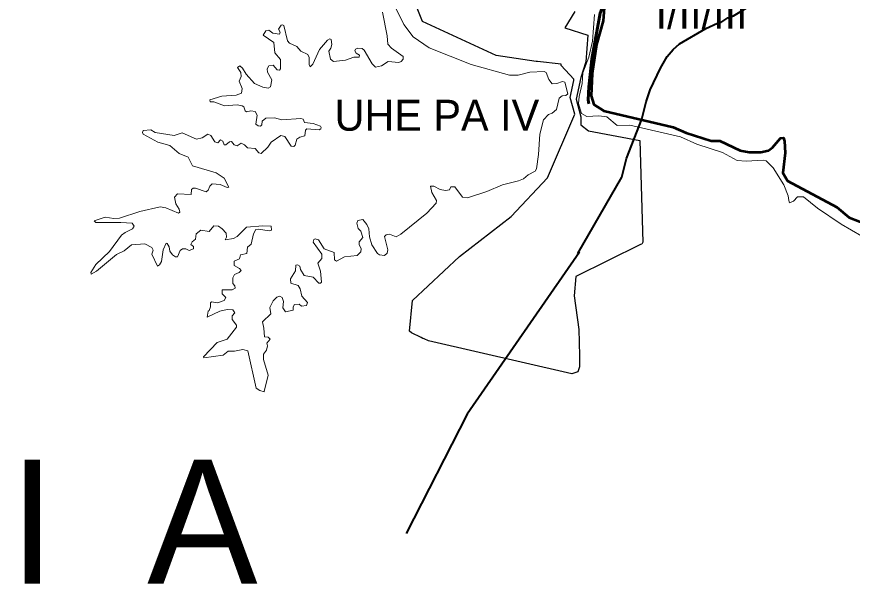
# Model space of a CAD drawing. Extents: x -1643653 to 4543381, y 1624270 to 13878484.
# Drawn here: x 578068 to 591570, y 8951061 to 8960281 of the extents above; entities that cross this region are included whole.
import ezdxf
from ezdxf.enums import TextEntityAlignment as Align

# ---------------------------------------------------------------- set-up
doc = ezdxf.new("R2010")
doc.units = 0
doc.header["$LTSCALE"] = 200
doc.linetypes.add('LONG_DASH_SHORT_DASH', pattern=[9.9, 6, -1.2, 1.5, -1.2])
for name, color, linetype, lineweight in [('12', 7, 'Continuous', 25), ('21', 7, 'Continuous', 25), ('25', 7, 'Continuous', 13), ('28', 7, 'Continuous', 53), ('60', 7, 'Continuous', 13), ('7', 7, 'LONG_DASH_SHORT_DASH', 60)]:
    doc.layers.add(name, color=color, linetype=linetype, lineweight=lineweight)
doc.layers.add('42', color=7, linetype='Continuous')

msp = doc.modelspace()

# ---------------------------------------------------------------- linework, layer by layer
at = {"layer": '12', "lineweight": 40}
for points in [[(587134, 8956453.8), (587843.6, 8957685.7), (587923.7, 8957988.5), (588169.9, 8958625.1), (588237, 8958904.7), (588304.1, 8959099.5), (588468, 8959448.9), (588578.9, 8959635.8), (588673.7, 8959750.1), (588777.5, 8959843.1), (589203.6, 8960089.7), (589393.4, 8960175.8), (589428.5, 8960178.5), (589560.1, 8960264.6), (589648.9, 8960297.2), (590059.4, 8960543.5), (591188.1, 8961101.4), (591408.7, 8961235.4), (591525.3, 8961280.9), (591868.7, 8961488.1), (592154.1, 8961587.2), (592311.1, 8961655)], [(587162.9, 8956477.1), (585344.2, 8953858.6), (584358.8, 8951929.6)]]:
    msp.add_lwpolyline(points, dxfattribs=at)
at = {"layer": '21'}
for points in [[(586058.4, 8957052.4), (586644.6, 8957678.4), (587088.5, 8958707.8), (587013.2, 8958975.6), (587068.3, 8959252.8), (587068.3, 8959273), (586866.5, 8959495), (586866.5, 8959515.2), (586483.1, 8959555.5), (586463, 8959555.5), (585817.3, 8959656.5), (584626.8, 8960201.4), (584162.8, 8961372.1)], [(587088.5, 8960362.9), (586927, 8960100.5)], [(586927, 8960100.5), (587293.7, 8959984.2), (587261.8, 8959553.8), (587182.2, 8959298.7), (587110, 8958948.6), (587182.2, 8958662.7), (587182.2, 8958533.5), (587309.6, 8958437.9), (588138.3, 8958278.5)], [(588138.3, 8958278.5), (588184.9, 8956636.2), (588170.1, 8956606.6), (588147.9, 8956599.2), (587104, 8956080.8), (587074.4, 8955769.7), (587148.4, 8955229.1)], [(587148.4, 8955229.1), (587155.8, 8955021.8), (587155.8, 8954992.1), (587163.2, 8954829.2), (587163.2, 8954644.1), (587163.2, 8954621.8), (587133.6, 8954540.4), (587037.4, 8954510.8), (584720.1, 8955044), (584653.5, 8955073.6), (584631.3, 8955081), (584601.7, 8955095.8), (584446.2, 8955169.9), (584416.6, 8955199.5), (584461, 8955695.7), (585223.6, 8956406.6), (586058.4, 8957052.4)]]:
    msp.add_lwpolyline(points, dxfattribs=at)
at = {"layer": '25'}
for points in [[(584187.7, 8960432.6), (584325.6, 8960152.6), (584476.5, 8959954.9), (584733.5, 8959776.4), (585408.8, 8959506.7), (586028.5, 8959334.8), (586169.5, 8959338.8), (586356.5, 8959383.4), (586592.2, 8959394), (586621.9, 8959377), (586666.5, 8959264.6), (586719.8, 8959198.7), (586794.3, 8959202.9), (586887.5, 8959234.6), (586924.3, 8959221.3), (586974.5, 8959033.2), (586938.3, 8959007.4), (586883.3, 8959001), (586832.3, 8958962.8), (586791.8, 8958780.2), (586717.8, 8958720.8), (586660.1, 8958701.3), (586577.3, 8958614.2), (586518, 8958381), (586500.9, 8958053.6), (586466.9, 8957824.2), (586445.4, 8957783.8), (586330.8, 8957724.2), (586254.3, 8957662.7), (586173.8, 8957626.7)], [(584187.7, 8960432.6), (584325.6, 8960152.6), (584476.5, 8959954.9), (584733.5, 8959776.4), (585408.8, 8959506.7), (586028.5, 8959334.8), (586169.5, 8959338.8), (586356.5, 8959383.4), (586592.2, 8959394), (586621.9, 8959377), (586666.5, 8959264.6), (586719.8, 8959198.7), (586794.3, 8959202.9), (586887.5, 8959234.6), (586924.3, 8959221.3), (586974.5, 8959033.2), (586938.3, 8959007.4), (586883.3, 8959001), (586832.3, 8958962.8), (586791.8, 8958780.2), (586717.8, 8958720.8), (586660.1, 8958701.3), (586577.3, 8958614.2), (586518, 8958381), (586500.9, 8958053.6), (586466.9, 8957824.2), (586445.4, 8957783.8), (586330.8, 8957724.2), (586254.3, 8957662.7), (586173.8, 8957626.7)], [(582299.4, 8960082.5), (582339.6, 8960143.8), (582362.8, 8960152.2), (582381.9, 8960139.6), (582443.6, 8959893.3), (582477.6, 8959853), (582596.3, 8959797.7), (582656.1, 8959725.5), (582771.8, 8959670.2), (582795.6, 8959619.4), (582792, 8959510.9), (582809, 8959470.7), (582851.4, 8959515.1), (582957.8, 8959753.2), (583089.5, 8959901.9), (583125.3, 8959922.9), (583148.8, 8959914.2), (583159.4, 8959833.8), (583144.6, 8959774.5), (583108.6, 8959723.3), (583108.6, 8959723.3), (583138.3, 8959595.9), (583184.5, 8959559.9), (583382, 8959578.8), (583514.4, 8959627.7), (583603.4, 8959628), (583607.5, 8959661.8), (583550.2, 8959691.6), (583531.3, 8959731.8), (583541.6, 8959757), (583580.3, 8959774.3), (583651.7, 8959765.9), (583684, 8959740.2), (583809.5, 8959521.5), (583862.6, 8959466.3), (583962.4, 8959487.6), (584070.6, 8959557.6), (584244.7, 8959542.8), (584281, 8959557.7), (584312.8, 8959595.8), (584315, 8959638.2), (584126, 8959774.3), (584064.3, 8959836.4), (584055.9, 8959969.5), (583979.3, 8960356.6)], [(582299.4, 8960082.5), (582339.6, 8960143.8), (582362.8, 8960152.2), (582381.9, 8960139.6), (582443.6, 8959893.3), (582477.6, 8959853), (582596.3, 8959797.7), (582656.1, 8959725.5), (582771.8, 8959670.2), (582795.6, 8959619.4), (582792, 8959510.9), (582809, 8959470.7), (582851.4, 8959515.1), (582957.8, 8959753.2), (583089.5, 8959901.9), (583125.3, 8959922.9), (583148.8, 8959914.2), (583159.4, 8959833.8), (583144.6, 8959774.5), (583108.6, 8959723.3), (583108.6, 8959723.3), (583138.3, 8959595.9), (583184.5, 8959559.9), (583382, 8959578.8), (583514.4, 8959627.7), (583603.4, 8959628), (583607.5, 8959661.8), (583550.2, 8959691.6), (583531.3, 8959731.8), (583541.6, 8959757), (583580.3, 8959774.3), (583651.7, 8959765.9), (583684, 8959740.2), (583809.5, 8959521.5), (583862.6, 8959466.3), (583962.4, 8959487.6), (584070.6, 8959557.6), (584244.7, 8959542.8), (584281, 8959557.7), (584312.8, 8959595.8), (584315, 8959638.2), (584126, 8959774.3), (584064.3, 8959836.4), (584055.9, 8959969.5), (583979.3, 8960356.6)], [(587403.7, 8960314.5), (587373.8, 8959887.7), (587311.1, 8959628.3), (587213.9, 8959375.4), (587204.9, 8959204), (587155.6, 8958993.5), (587145.5, 8958878.4), (587193.6, 8958719.2), (587281.8, 8958666.6), (587474.7, 8958681.2), (587603.9, 8958663), (587767.8, 8958525.1), (587976.7, 8958527.1), (588793.4, 8958337.9), (589059.2, 8958220.1), (589471.1, 8958087), (589708, 8957957.9), (589856.5, 8957947.6), (590127.1, 8957964.8), (590176.9, 8957951.8), (590291.3, 8957841.5), (590464.7, 8957564.3), (590533, 8957388.3), (590544.4, 8957313.3), (590557.7, 8957273.4), (590617.6, 8957300), (590684.2, 8957372.3), (590781.5, 8957369.6), (591005.6, 8957189.1), (591390.8, 8956926.9), (591724.8, 8956737.2)], [(587368.2, 8959365.5), (587437, 8959830.7), (587541.6, 8960215), (587558.8, 8960425)], [(580099.6, 8958407.9), (580098.5, 8958410.3), (580113.2, 8958444.3), (580235.9, 8958453.9), (580303, 8958410.4), (580612.5, 8958359.6), (580740.2, 8958401.9), (580973.9, 8958304.4), (581064.7, 8958323.4), (581156.5, 8958384.9), (581203.2, 8958359.3), (581270.9, 8958257.8), (581319.8, 8958245), (581360.2, 8958291.4), (581400.5, 8958268.1), (581420.4, 8958210.8), (581447.3, 8958208.8), (581504.7, 8958259.6), (581539.6, 8958263.8), (581539.6, 8958263.8), (581578.9, 8958209), (581627.9, 8958191.9), (581696, 8958236.1), (581748.9, 8958212.8), (581799.4, 8958164.3), (581920, 8958154), (581978.5, 8958081.4), (582019.4, 8958072.8), (582127.2, 8958170.8), (582178.1, 8958253.3), (582332.9, 8958361.5), (582401, 8958344.6), (582505.1, 8958189.8), (582543.4, 8958185.4), (582568.8, 8958204.3), (582596.6, 8958300), (582641.2, 8958331.9), (582721.7, 8958357.6), (582732.5, 8958448.5), (582755.7, 8958467.7), (582953.2, 8958455.2), (582983.1, 8958470.1), (582989.4, 8958491.2), (582974.4, 8958510.4), (582859.9, 8958554.9), (582719.7, 8958570.1), (582696.2, 8958625.2), (582656.2, 8958635.6), (582353.6, 8958614.5), (582235.7, 8958646.3), (582095.5, 8958639.9), (582031.7, 8958591.2), (582027, 8958531.6), (582005.7, 8958514.7), (581967.3, 8958516.9), (581933.7, 8958544.9), (581955, 8958692.5), (581922.9, 8958748.3), (581848.8, 8958761), (581780.6, 8958746.3), (581757.5, 8958761.1), (581738.2, 8958822.6), (581712.6, 8958841.7), (581627.9, 8958854.5), (581424.2, 8958839.7), (581251.8, 8958907.5), (581194.6, 8958907.9), (581190.6, 8958937.3), (581381.2, 8958994.6), (581615.1, 8959015.9), (581699.9, 8959047.7), (581708.6, 8959122.1), (581659.8, 8959239), (581692.1, 8959315.5), (581691.6, 8959378.9), (581634.5, 8959460), (581670.4, 8959485.2), (581717.2, 8959451.2), (581774.6, 8959353.5), (581908.3, 8959202.9), (582046.5, 8959141.3), (582129.4, 8959128.6), (582167.3, 8959147.5), (582188.6, 8959260.2), (582118.7, 8959385.4), (582116.5, 8959440.5), (582142.1, 8959487.4), (582214.1, 8959495.9), (582278, 8959423.9), (582316.1, 8959415.5), (582331, 8959439.1), (582330.8, 8959589.7), (582237.6, 8959695.7), (582220.4, 8959865.6), (582050.7, 8959980.4), (582091.2, 8960052.6), (582141.7, 8960063.2), (582208.1, 8960016.5), (582315.9, 8960001.7), (582322.5, 8960029), (582299.4, 8960082.5)], [(580099.6, 8958407.9), (580098.5, 8958410.3), (580113.2, 8958444.3), (580235.9, 8958453.9), (580303, 8958410.4), (580612.5, 8958359.6), (580740.2, 8958401.9), (580973.9, 8958304.4), (581064.7, 8958323.4), (581156.5, 8958384.9), (581203.2, 8958359.3), (581270.9, 8958257.8), (581319.8, 8958245), (581360.2, 8958291.4), (581400.5, 8958268.1), (581420.4, 8958210.8), (581447.3, 8958208.8), (581504.7, 8958259.6), (581539.6, 8958263.8), (581539.6, 8958263.8), (581578.9, 8958209), (581627.9, 8958191.9), (581696, 8958236.1), (581748.9, 8958212.8), (581799.4, 8958164.3), (581920, 8958154), (581978.5, 8958081.4), (582019.4, 8958072.8), (582127.2, 8958170.8), (582178.1, 8958253.3), (582332.9, 8958361.5), (582401, 8958344.6), (582505.1, 8958189.8), (582543.4, 8958185.4), (582568.8, 8958204.3), (582596.6, 8958300), (582641.2, 8958331.9), (582721.7, 8958357.6), (582732.5, 8958448.5), (582755.7, 8958467.7), (582953.2, 8958455.2), (582983.1, 8958470.1), (582989.4, 8958491.2), (582974.4, 8958510.4), (582859.9, 8958554.9), (582719.7, 8958570.1), (582696.2, 8958625.2), (582656.2, 8958635.6), (582353.6, 8958614.5), (582235.7, 8958646.3), (582095.5, 8958639.9), (582031.7, 8958591.2), (582027, 8958531.6), (582005.7, 8958514.7), (581967.3, 8958516.9), (581933.7, 8958544.9), (581955, 8958692.5), (581922.9, 8958748.3), (581848.8, 8958761), (581780.6, 8958746.3), (581757.5, 8958761.1), (581738.2, 8958822.6), (581712.6, 8958841.7), (581627.9, 8958854.5), (581424.2, 8958839.7), (581251.8, 8958907.5), (581194.6, 8958907.9), (581190.6, 8958937.3), (581381.2, 8958994.6), (581615.1, 8959015.9), (581699.9, 8959047.7), (581708.6, 8959122.1), (581659.8, 8959239), (581692.1, 8959315.5), (581691.6, 8959378.9), (581634.5, 8959460), (581670.4, 8959485.2), (581717.2, 8959451.2), (581774.6, 8959353.5), (581908.3, 8959202.9), (582046.5, 8959141.3), (582129.4, 8959128.6), (582167.3, 8959147.5), (582188.6, 8959260.2), (582118.7, 8959385.4), (582116.5, 8959440.5), (582142.1, 8959487.4), (582214.1, 8959495.9), (582278, 8959423.9), (582316.1, 8959415.5), (582331, 8959439.1), (582330.8, 8959589.7), (582237.6, 8959695.7), (582220.4, 8959865.6), (582050.7, 8959980.4), (582091.2, 8960052.6), (582141.7, 8960063.2), (582208.1, 8960016.5), (582315.9, 8960001.7), (582322.5, 8960029), (582299.4, 8960082.5)], [(591853.4, 8956904.4), (591520.9, 8957037.4), (591321.1, 8957200.7), (590522.6, 8957630), (590445.4, 8957756.5), (590486.6, 8958082.5), (590475.5, 8958269.4), (590460, 8958322.7), (590411.3, 8958320.8), (590281.4, 8958169.9), (590213.4, 8958120.7), (590089.5, 8958093.2), (589901.7, 8958091.4), (589756.1, 8958120.1), (589428.5, 8958275.3), (589288.6, 8958277.6), (588883.2, 8958402.7), (588677.6, 8958496.7), (587555.9, 8958762.2), (587392.7, 8958862), (587351, 8959003.1), (587368.2, 8959365.5)], [(579330.4, 8956970.9), (579320.1, 8956982.2), (579494.9, 8957040.3), (579635.1, 8957021.3), (579729, 8957025.6), (580056.8, 8957131.9), (580383.3, 8957210.3), (580477.4, 8957190.9), (580682.8, 8957104.2), (580701.6, 8957122.8), (580693.2, 8957169.7), (580640, 8957259.4), (580619.2, 8957363.6), (580667.8, 8957416.2), (580886.3, 8957410), (580890.9, 8957486.6), (580919.1, 8957507.7), (580955.2, 8957509.6), (581130.8, 8957450.5), (581162.8, 8957476.1), (581188.5, 8957544.2), (581224.5, 8957577.8), (581357.9, 8957571.4), (581466.2, 8957520.6), (581496, 8957526.9), (581421.8, 8957673.3), (581289.9, 8957760.6), (580910.1, 8957870.9), (580835.5, 8958013.2), (580692.5, 8958073.2), (580540.2, 8958198), (580349.1, 8958255.5), (580111.4, 8958382.8), (580099.6, 8958407.9)], [(579330.4, 8956970.9), (579320.1, 8956982.2), (579494.9, 8957040.3), (579635.1, 8957021.3), (579729, 8957025.6), (580056.8, 8957131.9), (580383.3, 8957210.3), (580477.4, 8957190.9), (580682.8, 8957104.2), (580701.6, 8957122.8), (580693.2, 8957169.7), (580640, 8957259.4), (580619.2, 8957363.6), (580667.8, 8957416.2), (580886.3, 8957410), (580890.9, 8957486.6), (580919.1, 8957507.7), (580955.2, 8957509.6), (581130.8, 8957450.5), (581162.8, 8957476.1), (581188.5, 8957544.2), (581224.5, 8957577.8), (581357.9, 8957571.4), (581466.2, 8957520.6), (581496, 8957526.9), (581421.8, 8957673.3), (581289.9, 8957760.6), (580910.1, 8957870.9), (580835.5, 8958013.2), (580692.5, 8958073.2), (580540.2, 8958198), (580349.1, 8958255.5), (580111.4, 8958382.8), (580099.6, 8958407.9)], [(586173.8, 8957626.7), (585918.1, 8957564.8), (585664, 8957458.9), (585351.4, 8957354.8), (585272.9, 8957365.6), (585149.7, 8957533.1), (585084, 8957533), (585058.5, 8957484.5), (584997.2, 8957473.7), (584911.7, 8957490.8), (584806, 8957543.7), (584753, 8957543.8), (584778.1, 8957437.9), (584848.5, 8957309.3), (584847.7, 8957267), (584696, 8957104.7), (584274.9, 8956764.4), (584197.5, 8956726), (584094.1, 8956768.4), (584038.7, 8956757.6), (584011.4, 8956727.3), (584062.2, 8956515.4), (584055.8, 8956462.4), (584011.2, 8956420.2), (583928.7, 8956432.8), (583896.6, 8956454.1), (583805.3, 8956596.4), (583767, 8956723.9), (583756.3, 8956851.3), (583724.4, 8956925.6), (583660.8, 8957002.1), (583580.2, 8956987.2), (583561.1, 8956946.9), (583586.5, 8956859.9), (583628.7, 8956817.4), (583660.7, 8956715.7), (583603.4, 8956642.9), (583599.3, 8956600.4), (583635.2, 8956528.2), (583628.9, 8956482), (583569.2, 8956422.2), (583365.5, 8956403), (583235.8, 8956333.2), (583204.2, 8956354.3), (583197.6, 8956473.1), (583036.3, 8956532.7), (582944.7, 8956675), (582889.9, 8956689.8), (582866.4, 8956681.3), (582857.8, 8956639.1), (583000.1, 8956445.4), (583000.1, 8956445.4), (582995.8, 8956371.3), (582932.2, 8956297.6), (582978.9, 8956171.6), (582991.4, 8955993), (582976.7, 8955976.2), (582947.1, 8955976.2), (582856.3, 8956071.3), (582711.3, 8956099.4), (582652.2, 8956196.2), (582645.2, 8956252.4), (582607.4, 8956273.4), (582579.8, 8956265), (582570.9, 8956175.6), (582492.5, 8956044.1), (582498.8, 8955974.4), (582613.2, 8955937.9), (582649.7, 8955884.6), (582675.3, 8955763.5), (582766.3, 8955661.9), (582751.6, 8955613.2), (582671.6, 8955604.4), (582632.4, 8955638.4), (582558.3, 8955632), (582532.9, 8955594), (582534.7, 8955540.7), (582411.8, 8955511), (582367.2, 8955576.8), (582379.8, 8955678.5), (582358.6, 8955744.6), (582321.7, 8955763.6), (582269.6, 8955750.9), (582214, 8955691.2), (582157.1, 8955581.8), (582171.5, 8955478.9), (582040.1, 8955351.6), (582061.2, 8955249.4), (582072.2, 8955107.3), (582129.2, 8955100.8), (582163, 8955071.2), (582108.2, 8955005.5), (582120.6, 8954960.7), (582103.7, 8954893.1), (582052.8, 8954828.8), (582057, 8954744.1), (582129.2, 8954489.4), (582066.7, 8954223.6)], [(586173.8, 8957626.7), (585918.1, 8957564.8), (585664, 8957458.9), (585351.4, 8957354.8), (585272.9, 8957365.6), (585149.7, 8957533.1), (585084, 8957533), (585058.5, 8957484.5), (584997.2, 8957473.7), (584911.7, 8957490.8), (584806, 8957543.7), (584753, 8957543.8), (584778.1, 8957437.9), (584848.5, 8957309.3), (584847.7, 8957267), (584696, 8957104.7), (584274.9, 8956764.4), (584197.5, 8956726), (584094.1, 8956768.4), (584038.7, 8956757.6), (584011.4, 8956727.3), (584062.2, 8956515.4), (584055.8, 8956462.4), (584011.2, 8956420.2), (583928.7, 8956432.8), (583896.6, 8956454.1), (583805.3, 8956596.4), (583767, 8956723.9), (583756.3, 8956851.3), (583724.4, 8956925.6), (583660.8, 8957002.1), (583580.2, 8956987.2), (583561.1, 8956946.9), (583586.5, 8956859.9), (583628.7, 8956817.4), (583660.7, 8956715.7), (583603.4, 8956642.9), (583599.3, 8956600.4), (583635.2, 8956528.2), (583628.9, 8956482), (583569.2, 8956422.2), (583365.5, 8956403), (583235.8, 8956333.2), (583204.2, 8956354.3), (583197.6, 8956473.1), (583036.3, 8956532.7), (582944.7, 8956675), (582889.9, 8956689.8), (582866.4, 8956681.3), (582857.8, 8956639.1), (583000.1, 8956445.4), (583000.1, 8956445.4), (582995.8, 8956371.3), (582932.2, 8956297.6), (582978.9, 8956171.6), (582991.4, 8955993), (582976.7, 8955976.2), (582947.1, 8955976.2), (582856.3, 8956071.3), (582711.3, 8956099.4), (582652.2, 8956196.2), (582645.2, 8956252.4), (582607.4, 8956273.4), (582579.8, 8956265), (582570.9, 8956175.6), (582492.5, 8956044.1), (582498.8, 8955974.4), (582613.2, 8955937.9), (582649.7, 8955884.6), (582675.3, 8955763.5), (582766.3, 8955661.9), (582751.6, 8955613.2), (582671.6, 8955604.4), (582632.4, 8955638.4), (582558.3, 8955632), (582532.9, 8955594), (582534.7, 8955540.7), (582411.8, 8955511), (582367.2, 8955576.8), (582379.8, 8955678.5), (582358.6, 8955744.6), (582321.7, 8955763.6), (582269.6, 8955750.9), (582214, 8955691.2), (582157.1, 8955581.8), (582171.5, 8955478.9), (582040.1, 8955351.6), (582061.2, 8955249.4), (582072.2, 8955107.3), (582129.2, 8955100.8), (582163, 8955071.2), (582108.2, 8955005.5), (582120.6, 8954960.7), (582103.7, 8954893.1), (582052.8, 8954828.8), (582057, 8954744.1), (582129.2, 8954489.4), (582066.7, 8954223.6)], [(579269.2, 8956128.5), (579267.5, 8956147.6), (579346.5, 8956275.5), (579569.6, 8956488.2), (579763, 8956751.6), (579818, 8956796.1), (579936.8, 8956853.3), (579964.5, 8956895.9), (579931, 8956942.9), (579750.3, 8956955.4), (579346.5, 8956953.4), (579330.4, 8956970.9)], [(579269.2, 8956128.5), (579267.5, 8956147.6), (579346.5, 8956275.5), (579569.6, 8956488.2), (579763, 8956751.6), (579818, 8956796.1), (579936.8, 8956853.3), (579964.5, 8956895.9), (579931, 8956942.9), (579750.3, 8956955.4), (579346.5, 8956953.4), (579330.4, 8956970.9)], [(581087.4, 8954777.9), (581086.2, 8954783.2), (581309.3, 8955015.9), (581466.6, 8955071.4), (581619.3, 8955264.8), (581619.2, 8955294.3), (581547.2, 8955390.1), (581547.2, 8955446.9), (581591.7, 8955496), (581559.6, 8955544.9), (581466.4, 8955547), (581352.5, 8955521.7), (581145.7, 8955426.2), (581160.6, 8955521.3), (581179.9, 8955534.8), (581200.8, 8955593.5), (581201, 8955657.4), (581215.8, 8955674.4), (581310.1, 8955657.7), (581421.9, 8955695.9), (581449.3, 8955742.7), (581390.1, 8955804.1), (581390.2, 8955865.7), (581551.4, 8955867.9), (581597.9, 8955895.3), (581593.8, 8955933.6), (581560, 8955969.8), (581562.1, 8956061.3), (581585.5, 8956114.1), (581661.8, 8956146.1), (581693.6, 8956177.9), (581665.8, 8956214.1), (581581.2, 8956260.8), (581578.8, 8956332.5), (581666, 8956369.2), (581685.3, 8956432.7), (581787.1, 8956452), (581795.2, 8956554.8), (581857.1, 8956604.5), (581891.2, 8956774.6), (581933.5, 8956840.4), (581969.4, 8956847.3), (582150.4, 8956819.5), (582182.3, 8956832.5), (582180, 8956896), (582043.8, 8956902.2), (581783.2, 8956880.5), (581783.2, 8956880.5), (581630, 8956728.1), (581572.6, 8956696.3), (581434.7, 8956673.2), (581455.8, 8956719.8), (581453.6, 8956783.3), (581388, 8956855.3), (581326.2, 8956893.7), (581251.9, 8956904.3), (581175.2, 8956811), (581041.6, 8956834.2), (580969.4, 8956772.7), (580958.6, 8956687.6), (580901.5, 8956645.2), (580882.6, 8956601.5), (580922.5, 8956566.6), (580922.4, 8956530.5), (580856.8, 8956505.1), (580801.5, 8956530.5), (580744, 8956530.4), (580708.6, 8956501.7), (580663.4, 8956403.2), (580631.7, 8956403.2), (580586.8, 8956433.1), (580540.2, 8956494.7), (580531.6, 8956562.6), (580499.8, 8956617.5), (580482.8, 8956619.5), (580431.9, 8956511.2), (580408.5, 8956324.5), (580372.3, 8956271.5), (580340.8, 8956252.5), (580251.5, 8956443.2), (580274.6, 8956509.1), (580253.4, 8956549.5), (580136.6, 8956613.3), (579924, 8956592), (579805, 8956498.6), (579677.6, 8956436.9), (579359.2, 8956171.6), (579269.9, 8956121.1), (579269.2, 8956128.5)], [(581087.4, 8954777.9), (581086.2, 8954783.2), (581309.3, 8955015.9), (581466.6, 8955071.4), (581619.3, 8955264.8), (581619.2, 8955294.3), (581547.2, 8955390.1), (581547.2, 8955446.9), (581591.7, 8955496), (581559.6, 8955544.9), (581466.4, 8955547), (581352.5, 8955521.7), (581145.7, 8955426.2), (581160.6, 8955521.3), (581179.9, 8955534.8), (581200.8, 8955593.5), (581201, 8955657.4), (581215.8, 8955674.4), (581310.1, 8955657.7), (581421.9, 8955695.9), (581449.3, 8955742.7), (581390.1, 8955804.1), (581390.2, 8955865.7), (581551.4, 8955867.9), (581597.9, 8955895.3), (581593.8, 8955933.6), (581560, 8955969.8), (581562.1, 8956061.3), (581585.5, 8956114.1), (581661.8, 8956146.1), (581693.6, 8956177.9), (581665.8, 8956214.1), (581581.2, 8956260.8), (581578.8, 8956332.5), (581666, 8956369.2), (581685.3, 8956432.7), (581787.1, 8956452), (581795.2, 8956554.8), (581857.1, 8956604.5), (581891.2, 8956774.6), (581933.5, 8956840.4), (581969.4, 8956847.3), (582150.4, 8956819.5), (582182.3, 8956832.5), (582180, 8956896), (582043.8, 8956902.2), (581783.2, 8956880.5), (581783.2, 8956880.5), (581630, 8956728.1), (581572.6, 8956696.3), (581434.7, 8956673.2), (581455.8, 8956719.8), (581453.6, 8956783.3), (581388, 8956855.3), (581326.2, 8956893.7), (581251.9, 8956904.3), (581175.2, 8956811), (581041.6, 8956834.2), (580969.4, 8956772.7), (580958.6, 8956687.6), (580901.5, 8956645.2), (580882.6, 8956601.5), (580922.5, 8956566.6), (580922.4, 8956530.5), (580856.8, 8956505.1), (580801.5, 8956530.5), (580744, 8956530.4), (580708.6, 8956501.7), (580663.4, 8956403.2), (580631.7, 8956403.2), (580586.8, 8956433.1), (580540.2, 8956494.7), (580531.6, 8956562.6), (580499.8, 8956617.5), (580482.8, 8956619.5), (580431.9, 8956511.2), (580408.5, 8956324.5), (580372.3, 8956271.5), (580340.8, 8956252.5), (580251.5, 8956443.2), (580274.6, 8956509.1), (580253.4, 8956549.5), (580136.6, 8956613.3), (579924, 8956592), (579805, 8956498.6), (579677.6, 8956436.9), (579359.2, 8956171.6), (579269.9, 8956121.1), (579269.2, 8956128.5)], [(582066.7, 8954223.6), (582065.2, 8954217.4), (581995.8, 8954238.9), (581939.2, 8954279.2), (581803.6, 8954880.3), (581719.8, 8954905.5), (581585.7, 8954873.7), (581483.7, 8954877.8), (581402.7, 8954812.1), (581089.5, 8954768.8), (581087.4, 8954777.9)], [(582066.7, 8954223.6), (582065.2, 8954217.4), (581995.8, 8954238.9), (581939.2, 8954279.2), (581803.6, 8954880.3), (581719.8, 8954905.5), (581585.7, 8954873.7), (581483.7, 8954877.8), (581402.7, 8954812.1), (581089.5, 8954768.8), (581087.4, 8954777.9)]]:
    msp.add_lwpolyline(points, dxfattribs=at)
at = {"layer": '28'}
for points in [[(588373.5, 8962049.1), (588387.5, 8962034), (588681.9, 8961493.8), (588630.6, 8961421.7), (588323.7, 8961300.9), (588213.5, 8961217.2), (587717.4, 8960723.2), (587596.7, 8960558.6), (587558.8, 8960425), (587541.6, 8960215), (587437, 8959830.7), (587368.2, 8959365.5)], [(587368.2, 8959365.5), (587351, 8959003.1), (587392.7, 8958862), (587555.9, 8958762.2), (588677.6, 8958496.7), (588883.2, 8958402.7), (589288.6, 8958277.6), (589428.5, 8958275.3), (589756.1, 8958120.1), (589901.7, 8958091.4), (590089.5, 8958093.2), (590213.4, 8958120.7), (590281.4, 8958169.9), (590411.3, 8958320.8), (590460, 8958322.7), (590475.5, 8958269.4), (590486.6, 8958082.5), (590445.4, 8957756.5), (590522.6, 8957630), (591321.1, 8957200.7), (591520.9, 8957037.4), (591853.4, 8956904.4)]]:
    msp.add_lwpolyline(points, dxfattribs=at)
at = {"layer": '60', "lineweight": 25}
msp.add_spline([(814781, 9009175.5), (814787.2, 9009173.4), (814796.9, 9009173.4), (814799.4, 9009172.4), (814805.1, 9009174.5), (814805.6, 9009176.5), (814811.7, 9009179.5), (814811.7, 9009179.5), (814801.5, 9009181), (814790.7, 9009181.5), (814784.1, 9009183.1), (814777.4, 9009185.1), (814778.4, 9009175.5)], degree=3, dxfattribs=at)
at = {"layer": '7'}
msp.add_lwpolyline([(587540.9, 8964040.5), (587545.5, 8964019), (587739.9, 8963466), (587828.5, 8963155), (587886.8, 8963016.8), (588023, 8962809.1), (588321.3, 8962515.1), (588353.7, 8962454.8), (588379.7, 8962350), (588349.5, 8962039.7), (588356.1, 8961913.4), (588409.9, 8961732.7), (588515.9, 8961598.5), (588533, 8961520.2), (588511.4, 8961464.3), (588140, 8961216), (587908.2, 8961023.1), (587733.4, 8960846.2), (587616.5, 8960660), (587498.3, 8960337.4), (587362.2, 8959603), (587314, 8959147.2), (587303.2, 8958935.8), (587310.7, 8958873)], dxfattribs=at)

# ---------------------------------------------------------------- texts
at = {"layer": '42'}
for s, p in [('I/II/III', (589134.4, 8960086.2)), ('UHE PA IV', (584857.3, 8958438.7))]:
    msp.add_text(s, height=500, dxfattribs=at).set_placement(p, align=Align.CENTER)
msp.add_text('B  A  H  I  A', height=2000, dxfattribs=at).set_placement((567989.8, 8951121.2))

doc.saveas('drawing.dxf')
